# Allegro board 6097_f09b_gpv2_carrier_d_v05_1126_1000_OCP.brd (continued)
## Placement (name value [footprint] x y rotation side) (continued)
R3205  27  [R0402]  74.14 58.86 0 top
R3206  27  [R0402]  74.14 60.13 0 top
R3207  27  [R0402]  74.14 61.65 0 top
R3208  27  [R0402]  74.14 62.92 0 top
R3209  27  [R0402]  74.14 64.45 0 top
R3210  27  [R0402]  74.14 65.72 0 top
R3212  33  [R0402]  83.6 33.14 0 top
R3213  33  [R0402]  80.9 31.7 270 top
R3214  33  [R0402]  92.58 32.88 0 top
R3215  33  [R0402]  79.76 31.7 90 top
R3216  4.75K  [R0402]  79.76 25.6 0 top
R3217  4.75K  [R0402]  81.92 31.7 270 top
R3218  1K  [R0402]  118.92 44.15 90 top
R3219  10K  [R0402]  89.2 37.47 180 top
R3220  1K  [R0402]  92.58 33.9 0 top
R3227  1M  [R0402]  115.49 39.7 270 top
R3228  1.69K  [R0402]  112.7 38.18 0 top
R3230  1K  [R0402]  125.91 37.41 180 top
R3231  1K  [R0402]  128.32 37.41 0 top
R3232  1K  [R0402]  125.91 36.4 180 top
R3233  1K  [R0402]  128.32 36.4 0 top
R3234  1K  [R0402]  125.88 41.48 180 top
R3235  1K  [R0402]  125.88 42.49 0 top
R3236  1K  [R0402]  124.16 44.15 270 top
R3237  1K  [R0402]  123.13 44.15 90 top
R3238  2.2K  [R0402]  131.79 36.12 0 top
R3239  2.2K  [R0402]  131.79 37.15 0 top
R3240  1K  [R0402]  128.32 35.38 0 top
R3241  100  [R0402]  194.11 80.04 0 bottom
R3242  0  [R0402]  81.73 33.94 180 top
R3250  33  [R0402]  205.39 53.57 0 top
R3251  33  [R0402]  202.69 51.65 270 bottom
R3252  33  [R0402]  203.79 51.67 270 bottom
R3253  33  [R0402]  201.55 50.89 270 bottom
R3254  33  [R0402]  200.47 50.91 270 bottom
R3255  33  [R0402]  205.37 54.66 0 top
R3256  4.7K  [R0402]  192.46 83.57 90 bottom
R3257  4.7K  [R0402]  200.75 83.3 180 bottom
R3258  4.7K  [R0402]  207.85 101.68 270 top
R3259  4.7K  [R0402]  207.92 58.93 0 top
R3260  4.7K  [R0402]  205.79 100.66 0 top
R3261  4.7K  [R0402]  205.79 99.57 0 top
R3264  15K  [R0402]  9.83 100.97 0 top
R3265  1K  [R0402]  9.83 105.24 0 top
R3266  33  [R0402]  9.83 102.03 180 top
R3268  150  [R0402]  9.84 106.31 180 top
R3269  150  [R0402]  206.73 108.08 90 top
R3270  0  [R0402]  9.83 103.13 180 top
R3271  4.75K  [R0402]  9.83 104.2 180 top
R3272  4.75K  [R0402]  192.58 73.03 270 bottom
R3273  4.75K  [R0402]  191.53 73.03 270 bottom
R3274  33  [R0402]  186.36 137.69 0 top
R3275  4.75K  [R0402]  186.36 135.62 0 top
R3276  4.75K  [R0402]  186.36 136.67 0 top
R3277  4.75K  [R0402]  181.93 131.06 0 top
R3278  4.75K  [R0402]  181.49 135.94 90 top
R3279  4.75K  [R0402]  181.5 137.87 270 top
R3280  33  [R0402]  186.36 133.58 0 top
R3281  0  [R0402]  205.79 102.74 180 top
R3282  0  [R0402]  205.79 103.76 180 top
R3284  4.75K  [R0402]  193.65 73.03 270 bottom
R3285  4.7K  [R0402]  205.79 101.7 0 top
R3287  22  [R0402]  200.95 84.92 270 bottom
R3288  22  [R0402]  203.65 84.85 270 bottom
R3289  22  [R0402]  202.17 84.77 270 bottom
R3290  22  [R0402]  206.5 70.98 0 top
R3291  22  [R0402]  206.5 68.95 0 top
R3292  22  [R0402]  206.5 72 0 top
R3293  22  [R0402]  206.5 69.96 0 top
R3294  22  [R0402]  205.49 70.1 0 bottom
R3295  22  [R0402]  205.49 73.15 0 bottom
R3296  22  [R0402]  205.49 72.14 0 bottom
R3297  22  [R0402]  205.49 71.12 0 bottom
R3298  22  [R0402]  205.49 69.09 0 bottom
R3301  4.7K  [R0402]  17.6 65.33 90 top
R3302  4.7K  [R0402]  16.59 65.33 90 top
R3332  33  [R0402]  143.15 44.65 180 bottom
R3333  33  [R0402]  143.15 43.51 180 bottom
R3334  33  [R0402]  128.42 42.62 180 bottom
R3335  33  [R0402]  128.42 41.1 180 bottom
R3336  1K  [R0402]  147.09 44.65 0 bottom
R3337  1K  [R0402]  147.09 43.51 0 bottom
R3430  4.7K  [R0402]  178.44 119.17 90 bottom
R3431  4.7K  [R0402]  179.65 119.2 90 bottom
R3432  4.7K  [R0402]  181.01 119.21 90 bottom
R3433  1K  [R0402]  178.43 116.94 270 bottom
R3434  1K  [R0402]  179.65 116.94 270 bottom
R3435  1K  [R0402]  181.01 116.92 270 bottom
R3437  412  [R0402]  96.21 144.89 90 top
R3474  0  [R0402]  23.38 19.68 180 top
R3511  22  [R0402]  23.83 85.75 270 bottom
R3512  22  [R0402]  19.68 85.72 270 bottom
R3513  22  [R0402]  15.57 85.72 270 bottom
R3514  22  [R0402]  15.77 98.86 90 bottom
R3515  22  [R0402]  181.88 128.93 0 top
R3516  22  [R0402]  20.07 103.27 180 top
R3517  22  [R0402]  172.62 125.3 180 top
R3518  22  [R0402]  172.62 122.25 180 top
R3519  22  [R0402]  185.7 120.35 0 top
R3520  22  [R0402]  20.08 102.24 180 top
R3521  22  [R0402]  190.78 124.41 0 top
R3522  22  [R0402]  190.78 126.44 0 top
R3523  22  [R0402]  181.88 129.94 180 top
R3524  22  [R0402]  181.88 125.88 180 top
R3525  22  [R0402]  172.62 123.27 0 top
R3526  22  [R0402]  186.72 123.39 180 top
R3527  22  [R0402]  186.72 125.43 180 top
R3528  22  [R0402]  186.72 127.46 180 top
R3529  22  [R0402]  28.86 88.52 180 bottom
R3530  22  [R0402]  22.76 85.72 90 bottom
R3531  22  [R0402]  18.67 85.72 90 bottom
R3532  22  [R0402]  18.85 98.86 270 bottom
R3533  22  [R0402]  21.89 98.86 270 bottom
R3534  22  [R0402]  26.82 96.88 180 bottom
R3535  100K  [R0402]  22.45 117.01 270 top
R3536  100K  [R0402]  47.14 116.71 270 top
R3537  100K  [R0402]  72.03 115.54 270 top
R3538  100K  [R0402]  97.44 116.34 270 top
R3539  100K  [R0402]  121.25 116.47 270 top
R3540  100K  [R0402]  148.98 115.92 270 top
R3541  100K  [R0402]  40.67 118.08 270 bottom
R3542  100K  [R0402]  63.34 115.31 270 bottom
R3543  100K  [R0402]  87.39 115.37 270 bottom
R3544  100K  [R0402]  113.72 115.46 270 bottom
R3545  100K  [R0402]  137.35 116.01 270 bottom
R3546  100K  [R0402]  164.61 118.76 270 bottom
R3551  0  [R0402]  197.1 34.74 0 top
R3552  22  [R0402]  197.1 33.73 0 top
R3565  4.7K  [R0402]  205.79 93.09 0 top
R3566  4.7K  [R0402]  205.79 94.18 0 top
R3567  4.7K  [R0402]  205.79 92.02 0 top
R3568  4.7K  [R0402]  205.79 90.98 0 top
R3569  4.7K  [R0402]  205.79 97.36 0 top
R3570  4.7K  [R0402]  205.79 98.45 0 top
R3571  4.7K  [R0402]  195.58 90.35 0 bottom
R3572  4.7K  [R0402]  205.79 95.28 0 top
R3573  4.7K  [R0402]  192.61 88.09 0 bottom
R3574  4.7K  [R0402]  205.79 96.32 0 top
R3575  4.7K  [R0402]  192.54 89.2 0 bottom
R3576  4.7K  [R0402]  194.01 88.06 270 bottom
R3577  0  [R0402]  52.43 66.21 180 top
R3578  0  [R0402]  52.43 64.94 180 top
R3579  0  [R0402]  52.43 63.41 180 top
R3580  0  [R0402]  52.43 62.14 180 top
R3581  0  [R0402]  52.43 60.62 180 top
R3582  0  [R0402]  52.43 59.35 180 top
R3583  0  [R0402]  52.43 57.82 180 top
R3584  0  [R0402]  52.43 56.55 180 top
R3585  0  [R0402]  58.35 50.3 270 top
R3586  0  [R0402]  59.62 50.3 270 top
R3587  0  [R0402]  61.4 50.3 270 top
R3588  0  [R0402]  62.67 50.3 270 top
R3589  0  [R0402]  64.32 50.3 270 top
R3590  0  [R0402]  65.59 50.3 270 top
R3591  0  [R0402]  67.12 50.3 270 top
R3592  0  [R0402]  68.39 50.3 270 top
R3593  0  [R0402]  76.3 56.06 0 top
R3594  0  [R0402]  76.3 57.33 0 top
R3595  0  [R0402]  76.3 58.86 0 top
R3596  0  [R0402]  76.3 60.13 0 top
R3597  0  [R0402]  76.3 61.65 0 top
R3598  0  [R0402]  76.3 62.92 0 top
R3599  0  [R0402]  76.3 64.45 0 top
R3600  0  [R0402]  76.3 65.72 0 top
R3601  4.7K  [R0402]  92.55 40.74 0 top
R3618  22  [R0402]  23.38 18.52 180 top
R3619  4.7K  [R0402]  34.42 110.41 90 top
R3620  22  [R0402]  41.3 113.26 270 top
R3621  22  [R0402]  40.13 110.44 180 top
R3622  4.7K  [R0402]  33.32 110.41 90 top
R3623  0.005  [R1206XK]  27.91 116.08 270 top
R3625  10  [R0402]  30.73 115.54 0 top
R3626  10  [R0402]  30.73 116.59 0 top
R3628  22  [R0402]  63.14 110.21 270 top
R3629  22  [R0402]  62.09 110.21 270 top
R3630  4.7K  [R0402]  56.3 113.84 0 top
R3631  0.005  [R1206XK]  52.65 116.41 270 top
R3632  10  [R0402]  55.39 115.77 0 top
R3633  10  [R0402]  55.39 116.79 0 top
R3634  4.7K  [R0402]  81.1 112.15 0 top
R3635  22  [R0402]  88.51 110.6 270 top
R3636  22  [R0402]  87.49 110.6 270 top
R3638  0.005  [R1206XK]  77.53 115.02 270 top
R3639  10  [R0402]  80.17 114.81 0 top
R3640  10  [R0402]  80.17 115.88 0 top
R3642  22  [R0402]  111.87 108.88 270 top
R3643  22  [R0402]  110.64 108.88 270 top
R3645  0.005  [R1206XK]  102.94 115.72 270 top
R3646  10  [R0402]  105.41 114.92 0 top
R3647  10  [R0402]  105.41 115.96 0 top
R3649  22  [R0402]  137.57 109.78 270 top
R3650  22  [R0402]  136.53 109.78 270 top
R3651  4.7K  [R0402]  130.15 111.7 90 top
R3652  0.005  [R1206XK]  126.87 115.91 270 top
R3653  10  [R0402]  129.31 115.05 0 top
R3654  10  [R0402]  129.31 116.09 0 top
R3656  22  [R0402]  162.89 125.94 90 top
R3657  22  [R0402]  163.93 125.94 90 top
R3658  4.7K  [R0402]  160.98 115.95 90 top
R3659  0.005  [R1206XK]  154.55 116.23 270 top
R3660  10  [R0402]  157.76 115.45 0 top
R3661  10  [R0402]  157.76 116.54 0 top
R3666  22  [R0402]  32.45 108.07 0 bottom
R3667  22  [R0402]  30.43 109.66 0 bottom
R3669  0.005  [R1206XK]  34.62 116.61 270 bottom
R3670  10  [R0402]  31.51 116.08 180 bottom
R3671  10  [R0402]  31.51 117.11 180 bottom
R3678  4.7K  [R0402]  38.67 110.77 180 bottom
R3691  4.7K  [R0402]  38.35 111.81 180 bottom
R3692  22  [R0402]  47.74 109.96 270 bottom
R3693  22  [R0402]  48.78 109.96 270 bottom
R3694  0.005  [R1206XK]  57.8 115.5 270 bottom
R3695  10  [R0402]  54.82 114.64 180 bottom
R3696  10  [R0402]  54.82 115.68 180 bottom
R3697  4.7K  [R0402]  50.94 109.96 90 bottom
R3698  4.7K  [R0402]  52.03 109.96 90 bottom
R3699  22  [R0402]  74.81 108.72 270 bottom
R3700  22  [R0402]  75.85 108.72 270 bottom
R3701  0.005  [R1206XK]  81.93 114.8 270 bottom
R3702  10  [R0402]  79.54 113.93 180 bottom
R3703  10  [R0402]  79.54 114.97 180 bottom
R3704  4.7K  [R0402]  78.02 108.72 90 bottom
R3705  4.7K  [R0402]  79.13 108.72 90 bottom
R3706  22  [R0402]  98.17 109.04 270 bottom
R3707  22  [R0402]  99.21 109.04 270 bottom
R3708  0.005  [R1206XK]  107.58 114.83 270 bottom
R3709  10  [R0402]  104.89 113.97 180 bottom
R3710  10  [R0402]  104.89 115.01 180 bottom
R3711  4.7K  [R0402]  101.35 109.04 90 bottom
R3712  4.7K  [R0402]  102.41 109.04 90 bottom
R3713  4.7K  [R0402]  56.3 112.78 0 top
R3714  22  [R0402]  123.45 105.66 0 bottom
R3715  22  [R0402]  123.45 106.7 0 bottom
R3716  0.005  [R1206XK]  131.4 115.29 270 bottom
R3717  10  [R0402]  128.74 114.43 180 bottom
R3718  10  [R0402]  128.74 115.47 180 bottom
R3719  4.7K  [R0402]  124.76 109.36 90 bottom
R3720  4.7K  [R0402]  125.79 109.36 90 bottom
R3721  22  [R0402]  149.23 112.44 270 bottom
R3722  22  [R0402]  150.27 112.44 270 bottom
R3723  0.005  [R1206XK]  158.82 118.18 270 bottom
R3724  10  [R0402]  156.32 117.6 180 bottom
R3725  10  [R0402]  156.32 118.64 180 bottom
R3726  4.7K  [R0402]  154.44 112.43 90 bottom
R3727  4.7K  [R0402]  155.53 112.43 90 bottom
R3728  4.7K  [R0402]  81.1 113.26 0 top
R3729  4.7K  [R0402]  106.76 111.57 90 top
R3730  4.7K  [R0402]  108.15 110.14 0 top
R3731  4.7K  [R0402]  132.08 110.44 0 top
R3732  4.7K  [R0402]  162 115.95 90 top
R3745  4.75K  [R0402]  50.37 29.51 90 bottom
R3746  10  [R0402]  51.47 29.51 270 bottom
R3747  4.75K  [R0402]  55.07 38.56 270 bottom
R3748  22  [R0402]  56.16 38.56 270 bottom
R3749  4.75K  [R0402]  45.79 29.51 90 bottom
R3750  10  [R0402]  47.88 29.51 270 bottom
R3751  4.75K  [R0402]  52.53 38.56 270 bottom
R3752  22  [R0402]  53.7 38.56 270 bottom
R3753  4.75K  [R0402]  54.74 29.51 90 bottom
R3754  10  [R0402]  56.79 29.51 270 bottom
R3755  4.75K  [R0402]  57.23 38.56 270 bottom
R3756  22  [R0402]  58.42 38.61 270 bottom
R3757  22  [R0402]  49.28 29.51 90 bottom
R3758  22  [R0402]  44.75 29.51 90 bottom
R3759  22  [R0402]  53.72 29.51 90 bottom
R3764  22  [R0402]  32.28 40.87 0 top
R3765  10K  [R0402]  32.36 35.51 90 top
R3766  0.51  [R0402]  29.69 37.57 90 top
R3767  22  [R0402]  34.81 39.53 0 bottom
R3768  22  [R0402]  34.06 36.4 90 bottom
R3769  22  [R0402]  53.34 51.08 180 bottom
R3770  22  [R0402]  53.37 49.99 180 bottom
R3771  22  [R0402]  39.17 36.42 90 top
R3772  22  [R0402]  45.42 36.45 90 top
R3773  22  [R0402]  33.57 56.59 270 top
R3774  22  [R0402]  34.67 56.59 270 top
R3775  22  [R0402]  35.76 56.59 270 top
R3776  22  [R0402]  36.86 56.59 270 top
R3777  22  [R0402]  47.45 36.45 90 bottom
R3778  22  [R0402]  48.46 36.45 90 top
R3779  22  [R0402]  52.73 42.88 180 top
R3780  22  [R0402]  52.73 43.89 180 top
R3781  22  [R0402]  52.73 40.84 180 bottom
R3782  22  [R0402]  52.73 40.84 180 top
R3783  22  [R0402]  50.57 41.86 180 top
R3784  22  [R0402]  52.73 41.86 180 top
R3786  1K  [R0402]  34.81 38.51 0 bottom
R3787  1K  [R0402]  35.13 36.4 90 bottom
R3788  1K  [R0402]  51.21 51.08 0 bottom
R3789  1K  [R0402]  51.21 49.99 0 bottom
R3790  2.2K  [R0402]  40.21 36.42 90 top
R3791  2.2K  [R0402]  44.4 36.45 90 top
R3792  2.2K  [R0402]  33.57 54.56 90 top
R3793  2.2K  [R0402]  34.67 54.56 90 top
R3794  2.2K  [R0402]  35.76 54.56 90 top
R3795  2.2K  [R0402]  36.86 54.56 90 top
R3796  2.2K  [R0402]  46.43 36.45 90 bottom
R3797  2.2K  [R0402]  47.45 36.45 90 top
R3798  2.2K  [R0402]  50.57 42.88 0 top
R3799  2.2K  [R0402]  50.57 43.89 0 top
R3800  2.2K  [R0402]  50.57 40.84 0 bottom
R3801  2.2K  [R0402]  50.57 40.84 0 top
R3802  220  [R0402]  40.03 54.56 270 top
R3803  10K  [R0402]  10.57 43.49 270 top
R3804  22  [R0402]  21.67 65.33 90 top
R3805  22  [R0402]  22.68 65.33 90 top
R3806  220  [R0402]  23.42 80.11 90 top
R3807  220  [R0402]  20.65 65.33 270 top
R3808  4.7K  [R0402]  22.25 82.17 270 top
R3809  22  [R0402]  29.81 109.75 90 top
R3810  22  [R0402]  30.86 109.7 90 top
R3811  22  [R0402]  56.74 107.46 90 bottom
R3812  22  [R0402]  55.66 109.03 90 bottom
R3813  22  [R0402]  83.8 106.16 90 bottom
R3814  22  [R0402]  82.26 108.26 0 bottom
R3815  22  [R0402]  101.67 105.42 180 bottom
R3816  22  [R0402]  100.63 106.88 0 bottom
R3817  22  [R0402]  30.3 61.64 90 top
R3818  22  [R0402]  31.32 61.64 90 top
R3819  220  [R0402]  31.88 76.22 270 top
R3820  220  [R0402]  29.29 61.64 270 top
R3821  4.7K  [R0402]  30.86 78 270 top
R3822  4.7K  [R0402]  28.27 61.64 90 top
R3823  4.7K  [R0402]  27.25 61.64 90 top
R3824  4.7K  [R0402]  25.22 61.64 90 top
R3825  4.7K  [R0402]  26.24 61.64 90 top
R3826  22  [R0402]  128.57 108.05 0 top
R3827  22  [R0402]  129.29 109.62 90 top
R3828  22  [R0402]  148.79 120.21 90 bottom
R3829  22  [R0402]  147.64 120.21 90 bottom
R3830  22  [R0402]  37.62 61.62 90 top
R3831  22  [R0402]  38.64 61.62 90 top
R3832  220  [R0402]  39.19 76.2 270 top
R3833  220  [R0402]  36.6 61.62 270 top
R3834  4.7K  [R0402]  38.18 77.98 270 top
R3835  4.7K  [R0402]  35.59 61.62 90 top
R3836  4.7K  [R0402]  34.57 61.62 90 top
R3837  4.7K  [R0402]  32.54 61.62 90 top
R3838  4.7K  [R0402]  33.56 61.62 90 top
R3839  22  [R0402]  155.46 105.36 180 bottom
R3840  22  [R0402]  157.17 106.47 180 bottom
R3841  22  [R0402]  140.66 108.34 0 top
R3842  22  [R0402]  142.1 109.64 180 top
R3843  22  [R0402]  25.44 26.67 180 top
R3844  22  [R0402]  25.44 27.68 180 top
R3845  220  [R0402]  25.55 40.64 90 top
R3846  220  [R0402]  23.04 32.99 90 bottom
R3847  4.7K  [R0402]  24.54 38.81 90 top
R3848  4.7K  [R0402]  22.02 32.99 270 bottom
R3849  4.7K  [R0402]  21.01 32.99 270 bottom
R3850  4.7K  [R0402]  18.97 32.99 270 bottom
R3851  4.7K  [R0402]  19.99 32.99 270 bottom
R3852  22  [R0402]  113.37 106.99 180 top
R3853  22  [R0402]  112.87 104.32 180 top
R3854  22  [R0402]  86.31 106.04 0 top
R3855  22  [R0402]  85.38 103.23 180 top
R3856  22  [R0402]  45.21 61.62 90 top
R3857  22  [R0402]  46.23 61.62 90 top
R3858  220  [R0402]  47.8 76.2 270 top
R3859  220  [R0402]  44.2 61.62 270 top
R3860  4.7K  [R0402]  46.79 76.2 90 top
R3861  4.7K  [R0402]  43.18 61.62 90 top
R3862  4.7K  [R0402]  42.16 61.62 90 top
R3863  4.7K  [R0402]  40.13 61.62 90 top
R3864  4.7K  [R0402]  41.15 61.62 90 top
R3865  22  [R0402]  62.63 106.15 270 bottom
R3866  22  [R0402]  61.59 106.73 270 bottom
R3867  22  [R0402]  43.36 107.98 0 top
R3868  22  [R0402]  40.79 107.89 180 top
R3869  22  [R0402]  29.82 80.85 90 top
R3870  22  [R0402]  30.84 80.85 90 top
R3871  220  [R0402]  31.39 95.43 270 top
R3872  220  [R0402]  28.8 80.85 270 top
R3873  4.7K  [R0402]  30.38 97.21 270 top
R3874  4.7K  [R0402]  27.79 80.85 90 top
R3875  4.7K  [R0402]  26.77 80.85 90 top
R3876  4.7K  [R0402]  24.74 80.85 90 top
R3877  4.7K  [R0402]  25.76 80.85 90 top
R3878  22  [R0402]  10.31 30.55 180 top
R3879  22  [R0402]  10.28 29.32 180 top
R3880  22  [R0402]  38.12 37.19 270 bottom
R3881  22  [R0402]  10.13 27.91 180 top
R3882  4.7K  [R0402]  8.1 31.8 0 top
R3883  4.7K  [R0402]  8.13 30.48 0 top
R3884  4.7K  [R0402]  8.13 27.91 0 top
R3885  22  [R0402]  52.48 43.18 270 bottom
R3887  4.7K  [R0402]  134.03 110.02 0 top
R3888  4.7K  [R0402]  165.02 125.92 90 top
R3889  4.7K  [R0402]  36.68 110.52 0 bottom
R3890  4.7K  [R0402]  53.59 108.48 90 bottom
R3891  4.7K  [R0402]  79.36 105.14 180 bottom
R3892  4.7K  [R0402]  104.8 107.34 180 bottom
R3893  4.7K  [R0402]  124.9 107.57 90 bottom
R3894  4.7K  [R0402]  153.16 109.55 0 bottom
R3899  4.7K  [R0402]  37.89 110.77 0 top
R3900  4.7K  [R0402]  56.44 111.68 180 top
R3901  4.7K  [R0402]  85.98 110.97 180 top
R3902  4.7K  [R0402]  108.43 108.51 0 top
R3903  51K  [R0402]  53.62 45.54 270 top
R3904  10K  [R0402]  52.6 45.54 90 top
R3905  8.25K  [R0402]  54.76 42.88 0 top
R3906  0  [R0402]  53.62 47.32 90 top
R3908  5.11K  [R0402]  54.76 41.86 180 top
R3909  10K  [R0402]  53.62 45.54 270 bottom
R3910  34K  [R0402]  52.6 45.54 90 bottom
R3911  22  [R0402]  46.15 56.57 90 bottom
R3912  22  [R0402]  49.48 55.84 90 bottom
R3913  10K  [R0402]  7.77 38.56 180 top
R3914  10K  [R0402]  8.03 40.97 180 top
R3915  10K  [R0402]  7.77 37.54 180 top
R3916  4.7K  [R0402]  7.9 43 0 top
R3917  22  [R0402]  11.84 39.57 270 bottom
R3918  22  [R0402]  12.88 39.57 270 bottom
R3919  22  [R0402]  14.94 39.6 270 bottom
R3920  22  [R0402]  13.89 39.6 270 bottom
R3921  22  [R0402]  18.01 39.88 270 bottom
R3922  4.7K  [R0402]  23.72 56.77 270 top
R3923  4.7K  [R0402]  20.07 39.65 270 bottom
R3924  22  [R0402]  28.51 49.96 180 bottom
R3925  22  [R0402]  28.53 51.21 180 bottom
R3926  22  [R0402]  28.9 53.95 180 bottom
R3927  22  [R0402]  28.91 52.72 180 bottom
R3928  22  [R0402]  28.89 55.5 180 bottom
R3929  22  [R0402]  28.9 56.98 180 bottom
R3930  22  [R0402]  24.09 50.34 180 top
R3931  22  [R0402]  24.09 52.45 180 top
R3932  22  [R0402]  24.09 53.47 180 top
R3933  22  [R0402]  28.9 57.99 180 bottom
R3934  22  [R0402]  24.09 51.43 180 top
R3935  22  [R0402]  24.09 54.48 180 top
R3936  22  [R0402]  9.91 35.59 270 bottom
R3937  22  [R0402]  15.58 46.25 0 top
R3938  22  [R0402]  13.15 42.24 0 top
R3939  22  [R0402]  3.06 49.01 0 bottom
R3940  22  [R0402]  3.07 44.02 0 bottom
R3941  22  [R0402]  3.07 45.03 0 bottom
R3942  22  [R0402]  3.06 50.03 0 bottom
R3943  22  [R0402]  5.36 47.32 0 top
R3944  22  [R0402]  3.07 46.05 0 bottom
R3945  22  [R0402]  3.06 47.86 0 bottom
R3946  22  [R0402]  3.06 51.05 0 bottom
R3947  22  [R0402]  2.01 52.19 0 bottom
R3948  22  [R0402]  5.36 48.34 0 top
R3949  22  [R0402]  5.36 50.37 0 top
R3950  22  [R0402]  5.36 49.35 0 top
R3951  22  [R0402]  3.44 54.07 0 bottom
R3952  22  [R0402]  5.36 53.42 0 top
R3953  22  [R0402]  5.36 52.4 0 top
R3954  22  [R0402]  3.43 55.82 0 bottom
R3955  22  [R0402]  5.36 56.46 0 top
R3956  22  [R0402]  5.36 55.45 0 top
R3957  22  [R0402]  5.36 58.5 0 top
R3958  22  [R0402]  3.43 56.84 0 bottom
R3959  22  [R0402]  3.43 57.86 0 bottom
R3960  22  [R0402]  5.36 54.43 0 top
R3961  22  [R0402]  5.36 57.48 0 top
R3962  22  [R0402]  3.43 58.87 0 bottom
R3963  22  [R0402]  12.52 65.96 90 bottom
R3964  22  [R0402]  7.95 65.96 90 bottom
R3965  22  [R0402]  9.09 65.96 90 bottom
R3966  22  [R0402]  13.67 65.96 90 bottom
R3967  22  [R0402]  10.31 62.05 90 top
R3968  22  [R0402]  14.81 65.96 90 bottom
R3969  22  [R0402]  15.95 65.96 90 bottom
R3970  22  [R0402]  10.24 65.96 90 bottom
R3971  22  [R0402]  11.38 65.96 90 bottom
R3972  22  [R0402]  12.34 62.05 90 top
R3973  22  [R0402]  17.09 65.96 90 bottom
R3974  22  [R0402]  11.33 62.05 90 top
R3975  22  [R0402]  18.24 65.96 90 bottom
R3976  22  [R0402]  13.36 62.05 90 top
R3977  22  [R0402]  14.38 62.05 90 top
R3978  22  [R0402]  16.41 62.05 90 top
R3979  22  [R0402]  19.38 65.96 90 bottom
R3980  22  [R0402]  17.42 62.05 90 top
R3981  22  [R0402]  18.38 58.37 0 top
R3982  22  [R0402]  21.67 65.96 90 bottom
R3983  22  [R0402]  22.81 65.91 90 bottom
R3984  22  [R0402]  15.39 62.05 90 top
R3985  22  [R0402]  18.44 62.05 90 top
R3986  22  [R0402]  20.52 65.96 90 bottom
R3987  22  [R0402]  16.99 40.04 270 bottom
R3988  22  [R0402]  19.02 39.62 270 bottom
R3989  22  [R0402]  15.98 40.01 270 bottom
R3990  22  [R0402]  37.9 54.56 270 top
R3991  22  [R0402]  34.17 47.7 0 bottom
R3992  22  [R0402]  32.61 45.03 0 bottom
R3993  22  [R0402]  38.36 51.3 270 bottom
R3994  22  [R0402]  41.27 36.45 90 top
R3995  22  [R0402]  40.21 37.21 90 bottom
R3996  22  [R0402]  42.32 36.45 90 top
R3997  22  [R0402]  43.36 36.45 90 top
R3998  22  [R0402]  41.27 37.24 90 bottom
R3999  22  [R0402]  42.32 37.24 90 bottom
R4000  22  [R0402]  38.96 54.56 270 top
R4001  22  [R0402]  38.13 36.1 90 top
R4002  22  [R0402]  46.43 36.45 90 top
R4003  22  [R0402]  48.46 36.45 90 bottom
R4004  22  [R0402]  45.41 36.45 90 bottom
R4005  22  [R0402]  44.4 36.45 90 bottom
R4006  22  [R0402]  39.14 36.53 90 bottom
R4007  22  [R0402]  29.69 44.15 0 top
R4008  22  [R0402]  32.28 42.98 0 bottom
R4009  22  [R0402]  29.77 47.24 0 top
R4010  22  [R0402]  30.57 49.33 0 top
R4011  22  [R0402]  30.57 48.31 0 top
R4012  22  [R0402]  32.28 46.05 0 bottom
R4013  22  [R0402]  29.74 43.14 0 top
R4014  22  [R0402]  29.62 46.22 0 top
R4015  22  [R0402]  29.74 42.12 0 top
R4016  22  [R0402]  37.89 109.75 0 top
R4017  22  [R0402]  56.44 110.59 180 top
R4018  22  [R0402]  85.98 109.93 180 top
R4019  22  [R0402]  106.55 108.51 180 top
R4020  22  [R0402]  132.1 109.39 180 top
R4021  22  [R0402]  163.8 128.4 180 top
R4022  22  [R0402]  36.68 109.49 0 bottom
R4023  22  [R0402]  55.55 106.07 0 bottom
R4024  22  [R0402]  81.21 105.14 0 bottom
R4025  22  [R0402]  106.58 107.34 0 bottom
R4026  22  [R0402]  125.96 107.57 90 bottom
R4027  22  [R0402]  153.16 107.39 0 bottom
R4028  22  [R0402]  32.28 44.02 0 bottom
R4029  22  [R0402]  32.28 41.94 0 bottom
R4030  22  [R0402]  32.28 41.94 0 top
R4031  22  [R0402]  32.28 40.87 0 bottom
R4032  22  [R0402]  52.81 52.98 180 top
R4033  22  [R0402]  53.37 47.96 180 bottom
R4034  22  [R0402]  100.23 41.15 90 bottom
R4035  22  [R0402]  42.21 54.56 90 bottom
R4048  10K  [R0402]  4.09 9.09 0 top
R4049  22  [R0402]  145.19 44.65 0 bottom
R4050  22  [R0402]  145.19 43.51 0 bottom
R4051  1K  [R0402]  45.42 54.42 90 bottom
R4052  1K  [R0402]  48.39 55.84 270 bottom
R4053  22  [R0402]  51.21 48.97 180 bottom
R4054  22  [R0402]  42.21 54.56 270 top
R4055  4.7K  [R0402]  53.37 48.97 180 bottom
R4056  4.7K  [R0402]  42.21 56.39 270 top
R4057  22  [R0402]  6.77 82.6 0 bottom
R4058  22  [R0402]  3.6 84.15 0 bottom
R4059  22  [R0402]  4.01 78.99 90 bottom
R4060  22  [R0402]  2.22 73.28 90 top
R4061  22  [R0402]  7.14 90.45 0 bottom
R4062  22  [R0402]  3.63 90.66 0 bottom
R4063  22  [R0402]  67.57 40.29 270 bottom
R4064  22  [R0402]  65.39 40.29 270 bottom
R4065  4.75K  [R0402]  71.86 33.55 90 bottom
R4066  10  [R0402]  74.9 33.55 270 bottom
R4067  4.75K  [R0402]  66.46 40.29 270 bottom
R4068  22  [R0402]  72.87 33.55 90 bottom
R4069  4.75K  [R0402]  67.79 33.55 90 bottom
R4070  10  [R0402]  70.84 33.55 270 bottom
R4071  4.75K  [R0402]  64.28 40.29 270 bottom
R4072  22  [R0402]  68.81 33.55 90 bottom
R4073  4.7K  [R0402]  208 88.69 0 top
R4074  4.7K  [R0402]  208 89.77 0 top
R4075  1K  [R0402]  205.92 88.69 180 top
R4076  1K  [R0402]  205.92 89.77 180 top
R4077  47  [R0402]  3.61 83.07 0 bottom
R4078  47  [R0402]  6.77 83.64 0 bottom
R4079  47  [R0402]  4.55 74.5 90 bottom
R4080  47  [R0402]  1.96 78.99 270 bottom
R4081  47  [R0402]  3.63 89.58 0 bottom
R4082  47  [R0402]  11.13 93.55 0 top
R4083  47  [R0402]  3.67 92.74 0 bottom
R4084  47  [R0402]  8.23 95.91 0 bottom
R4085  47  [R0402]  3.6 86.24 0 bottom
R4086  47  [R0402]  7.14 88.87 0 bottom
R4087  47  [R0402]  3.73 96.93 0 bottom
R4088  47  [R0402]  8.23 99.31 0 bottom
R4089  22  [R0402]  8.23 94.89 0 bottom
R4090  22  [R0402]  3.78 94.79 0 bottom
R4091  22  [R0402]  6.99 87.05 0 bottom
R4092  22  [R0402]  3.6 87.32 180 bottom
R4093  22  [R0402]  8.23 98.27 0 bottom
R4094  22  [R0402]  3.71 98.98 0 bottom
R4095  22  [R0402]  14.59 48.32 180 top
R4096  22  [R0402]  14.83 43.54 270 top
R4097  1K  [R0402]  95.15 144.89 270 top
R4098  4.7K  [R0201]  21.55 123.27 90 top
R4099  4.7K  [R0201]  20.63 123.27 90 top
R4100  4.7K  [R0201]  22.91 133.15 180 bottom
R4101  4.7K  [R0201]  24.37 133.15 0 bottom
R4102  4.7K  [R0201]  51.16 145.04 180 bottom
R4103  4.7K  [R0201]  53.07 145.04 180 bottom
R4104  4.7K  [R0201]  53.07 143.99 0 bottom
R4105  4.7K  [R0201]  51.16 143.99 0 bottom
R4106  4.7K  [R0201]  62.21 145.09 180 bottom
R4107  4.7K  [R0201]  60.31 145.09 180 bottom
R4108  4.7K  [R0201]  60.31 144.04 0 bottom
R4109  4.7K  [R0201]  62.21 144.04 0 bottom
R4110  4.7K  [R0201]  70.04 145.06 180 bottom
R4111  4.7K  [R0201]  68.39 145.01 180 bottom
R4112  4.7K  [R0201]  68.39 143.96 0 bottom
R4113  4.7K  [R0201]  70.04 144.01 0 bottom
R4114  4.7K  [R0201]  130.82 145.09 0 top
R4115  4.7K  [R0201]  129.23 143.08 180 top
R4116  4.7K  [R0201]  127.85 143.08 180 top
R4117  4.7K  [R0201]  130.82 144.04 180 top
R4118  4.7K  [R0201]  143.9 144.56 180 bottom
R4119  4.7K  [R0201]  142.17 144.58 0 bottom
R4120  4.7K  [R0201]  142.17 143.61 180 bottom
R4121  4.7K  [R0201]  143.9 143.58 0 bottom
R4122  4.7K  [R0201]  172.43 126.87 90 bottom
R4123  4.7K  [R0201]  171.37 126.87 90 bottom
R4124  4.7K  [R0201]  171.38 128.69 90 bottom
R4125  4.7K  [R0201]  172.44 128.69 90 bottom
R4126  4.7K  [R0201]  146.25 144.61 0 bottom
R4127  4.7K  [R0201]  147.97 144.59 180 bottom
R4128  4.7K  [R0201]  147.97 143.62 0 bottom
R4129  4.7K  [R0201]  146.25 143.64 180 bottom
R4130  4.7K  [R0201]  127.86 145.09 0 top
R4131  4.7K  [R0201]  129.24 145.09 180 top
R4132  4.7K  [R0201]  129.24 144.04 0 top
R4133  4.7K  [R0201]  127.86 144.04 180 top
R4134  4.7K  [R0201]  71.71 145.09 180 bottom
R4135  4.7K  [R0201]  73.39 145.09 180 bottom
R4136  4.7K  [R0201]  73.39 144.04 0 bottom
R4137  4.7K  [R0201]  71.71 144.04 0 bottom
R4138  4.7K  [R0201]  65.08 144.99 180 bottom
R4139  4.7K  [R0201]  66.73 144.99 180 bottom
R4140  4.7K  [R0201]  66.73 143.93 0 bottom
R4141  4.7K  [R0201]  65.08 143.93 0 bottom
R4142  4.7K  [R0201]  48.1 129.65 180 bottom
R4143  4.7K  [R0201]  48.1 130.57 180 bottom
R4144  4.7K  [R0201]  47.84 144.12 0 bottom
R4145  4.7K  [R0201]  47.79 145.19 0 bottom
R4146  22  [R0402]  74 49.33 180 bottom
R4147  22  [R0402]  74 50.36 180 bottom
R4148  22  [R0402]  74 51.38 180 bottom
R4149  22  [R0402]  74 52.41 180 bottom
R4150  22  [R0402]  73.99 53.45 180 bottom
R4151  22  [R0402]  73.99 54.5 180 bottom
R4152  22  [R0402]  75.09 57.18 90 bottom
R4153  22  [R0402]  76.13 57.18 90 bottom
R4154  22  [R0402]  79.88 56.65 90 bottom
R4155  22  [R0402]  80.9 56.65 90 bottom
R4156  22  [R0402]  81.93 56.65 90 bottom
R4157  22  [R0402]  83.35 55.62 90 bottom
R4158  220  [R0402]  84.42 49.94 90 bottom
R4159  22  [R0402]  82.11 46.35 90 bottom
R4160  22  [R0402]  83.13 46.35 90 bottom
R4161  220  [R0402]  77.8 46.35 90 bottom
R4162  220  [R0402]  76.76 46.35 90 bottom
R4163  4.7K  [R0402]  78.84 46.35 270 bottom
R4164  22  [R0402]  181.61 126.67 180 bottom
R4165  22  [R0402]  186.38 136.32 180 bottom
R4166  22  [R0402]  184.68 130.99 180 bottom
R4167  22  [R0402]  191.9 127.18 90 bottom
R4168  22  [R0402]  193.29 104.8 0 bottom
R4169  22  [R0402]  190.47 143.51 90 bottom
R4170  22  [R0402]  188.09 143.51 90 bottom
R4171  22  [R0402]  185.83 124.77 90 bottom
R4172  22  [R0402]  188.16 121.72 90 bottom
R4173  22  [R0402]  191.62 143.51 90 bottom
R4174  22  [R0402]  189.2 121.72 90 bottom
R4175  22  [R0402]  189.28 143.51 90 bottom
R4182  4.7K  [R0402]  184.68 129.92 180 bottom
R4183  4.7K  [R0402]  191.9 125.4 270 bottom
R4184  4.7K  [R0402]  190.47 141.66 270 bottom
R4185  4.7K  [R0402]  191.62 141.66 270 bottom
R4186  4.7K  [R0402]  181.61 125.58 180 bottom
R4187  4.7K  [R0402]  186.36 134.59 180 bottom
R4188  4.7K  [R0402]  185.83 122.96 270 bottom
R4189  4.7K  [R0402]  188.16 119.81 270 bottom
R4190  4.7K  [R0402]  189.2 119.84 270 bottom
R4191  4.7K  [R0402]  189.28 141.63 270 bottom
R4192  4.7K  [R0402]  193.29 105.89 0 bottom
R4193  4.7K  [R0402]  188.09 141.63 270 bottom
R4194  22  [R0402]  32.23 86.33 90 top
R4195  22  [R0402]  35.38 81.33 180 top
R4196  22  [R0402]  40.79 81.36 0 top
R4197  22  [R0402]  89.26 60.78 180 top
R4198  22  [R0402]  93.04 55.22 180 top
R4199  22  [R0402]  89.26 58.37 180 top
R4200  22  [R0402]  102.69 56.95 0 top
R4201  22  [R0402]  102.67 60.12 0 top
R4202  22  [R0402]  40.21 87.91 0 top
R4203  22  [R0402]  89.26 55.19 180 top
R4204  22  [R0402]  40.18 85.62 0 top
R4205  22  [R0402]  31.93 91.03 90 top
R4206  4.7K  [R0402]  38.96 81.36 180 top
R4207  4.7K  [R0402]  89.26 59.49 180 top
R4208  4.7K  [R0402]  89.26 57.33 180 top
R4209  4.7K  [R0402]  89.26 56.29 180 top
R4210  4.7K  [R0402]  32.23 84.51 270 top
R4211  4.7K  [R0402]  37.16 81.33 0 top
R4212  4.7K  [R0402]  102.67 59.06 0 top
R4213  4.7K  [R0402]  40.21 88.95 0 top
R4214  4.7K  [R0402]  40.18 86.67 0 top
R4215  4.7K  [R0402]  31.93 89.23 270 top
R4216  4.7K  [R0402]  94.87 55.22 0 top
R4217  4.7K  [R0402]  102.69 58.04 0 top
R4218  10K  [R0402]  8.28 28.02 270 bottom
R4219  0  [R0603]  2.39 38.68 0 bottom
R4220  100K  [R0402]  2.18 33.81 0 bottom
R4221  100K  [R0402]  3.96 33.81 0 bottom
R4222  100K  [R0402]  7.24 28.02 270 bottom
R4223  100K  [R0402]  5.74 33.83 0 bottom
R4224  100K  [R0402]  7.59 33.83 0 bottom
R4225  100K  [R0402]  13.06 28.14 270 bottom
R4226  10K  [R0402]  12.04 28.14 270 bottom
R4227  0  [R0603]  6.4 38.68 180 bottom
R4228  22  [R0402]  53.34 49.12 180 top
R4229  22  [R0402]  53.34 50.17 180 top
R4230  10K  [R0402]  9.35 28.02 90 bottom
R4231  10K  [R0402]  14.25 28.14 90 bottom
R4232  22  [R0402]  111.16 143.83 90 top
R4233  1K  [R0402]  109.25 146.41 180 top
R4234  0  [R0402]  21.98 135.87 270 bottom
R4235  0  [R0402]  37.03 136.17 0 top
R4236  0  [R0402]  50.67 122.33 90 top
R4237  0  [R0402]  61.83 135.97 180 top
R4238  0  [R0402]  75.18 122.37 90 top
R4239  0  [R0402]  79.62 136.06 0 top
R4240  0  [R0402]  77.35 144.25 180 bottom
R4241  0  [R0402]  110.13 136.13 180 top
R4242  0  [R0402]  122.22 121.88 90 top
R4243  0  [R0402]  133.77 136.02 0 top
R4244  0  [R0402]  147.02 121.34 90 top
R4245  0  [R0402]  155.88 135.98 0 top
R4246  0  [R0402]  160.54 125.18 90 bottom
R4247  0  [R0402]  150.67 143.96 270 bottom
R4248  0  [R0402]  149.58 143.99 270 bottom
R4249  0  [R0402]  128.51 145.04 180 bottom
R4250  0  [R0402]  112.84 125.57 0 bottom
R4251  0  [R0402]  95.19 143.22 0 top
R4252  0  [R0402]  89.63 125.27 90 bottom
R4253  0  [R0402]  77.35 143.24 180 bottom
R4254  0  [R0402]  77.35 145.28 180 bottom
R4255  0  [R0402]  54.77 143.3 180 bottom
R4256  0  [R0402]  34.89 145.61 0 bottom
R4257  0  [R0402]  29.62 143.9 180 bottom
R4258  33  [R0402]  198.33 7.56 90 bottom
R4259  33  [R0402]  199.07 10.92 0 bottom
R4260  33  [R0402]  194.03 17.17 270 bottom
R4261  33  [R0402]  192.97 17.17 270 bottom
R4262  4.7K  [R0402]  30.71 121.11 270 top
R4263  4.7K  [R0402]  53.24 121.37 270 top
R4264  4.7K  [R0402]  77.5 120.73 270 top
R4265  4.7K  [R0402]  98.99 121.1 270 top
R4266  4.7K  [R0402]  125.92 121.26 270 top
R4267  4.7K  [R0402]  148.52 120.55 270 top
R4268  4.7K  [R0402]  156.74 124.2 270 bottom
R4269  4.7K  [R0402]  135.92 124.2 270 bottom
R4270  4.7K  [R0402]  111.28 124.16 270 bottom
R4271  4.7K  [R0402]  88.24 124.21 270 bottom
R4272  4.7K  [R0402]  64.28 123.7 270 bottom
R4273  4.7K  [R0402]  41.59 123.15 270 bottom
R4274  4.7K  [R0402]  17.76 44.93 0 top
R4275  4.7K  [R0402]  8.59 82.6 180 bottom
R4276  4.7K  [R0402]  6.76 84.73 180 bottom
R4277  4.7K  [R0402]  2.97 78.99 90 bottom
R4278  4.7K  [R0402]  3.3 73.28 90 top
R4279  4.7K  [R0402]  7.14 91.52 0 bottom
R4280  4.7K  [R0402]  7.11 92.56 180 bottom
R4281  4.7K  [R0402]  10.03 94.89 180 bottom
R4282  4.7K  [R0402]  3.78 93.78 0 bottom
R4283  4.7K  [R0402]  6.99 86.03 0 bottom
R4284  4.7K  [R0402]  1.55 88.27 270 top
R4285  4.7K  [R0402]  8.23 97.26 0 bottom
R4286  4.7K  [R0402]  3.71 97.97 0 bottom
R4287  100K  [R0402]  103.41 136.34 180 top
R4288  22  [R0402]  15.73 91.63 270 top
R4289  0  [R0402]  12.22 97.03 90 top
R4290  10K  [R0402]  5.56 102.79 90 bottom
R4292  0  [R0402]  6.33 100.91 270 bottom
R4293  0  [R0603]  1.72 105.65 90 bottom
R4294  0  [R0402]  31.81 122.54 90 top
R4295  0  [R0402]  56.29 122.86 90 top
R4296  0  [R0402]  80.32 122.8 90 top
R4297  0  [R0402]  102.85 122.08 90 top
R4298  0  [R0402]  128.2 123.18 180 top
R4299  0  [R0402]  152.42 123.08 90 top
R4300  0  [R0402]  155.72 128.46 90 bottom
R4301  0  [R0402]  131.79 128.14 90 bottom
R4302  0  [R0402]  107.17 128.46 90 bottom
R4303  0  [R0402]  83.65 127.11 90 bottom
R4304  0  [R0402]  59.96 127.36 90 bottom
R4305  0  [R0402]  32.34 126.59 90 bottom
R4308  0.001  [R1206XA]  180.09 43.3 0 bottom
R4309  0.001  [R1206XA]  184.5 47.3 0 top
R4311  0.001  [R1206XA]  184.5 47.3 0 bottom
R4312  4.7K  [R0402]  36.3 109.57 270 top
R4313  4.7K  [R0402]  58.48 109.54 90 top
R4314  4.7K  [R0402]  82.51 108.8 0 top
R4315  4.7K  [R0402]  84.87 106.43 270 bottom
R4316  4.7K  [R0402]  58.68 107.56 270 bottom
R4317  4.7K  [R0402]  39.08 109.22 180 bottom
R4318  4.7K  [R0402]  102.39 108.45 0 top
R4319  4.7K  [R0402]  127.51 110.26 90 top
R4320  4.7K  [R0402]  161.52 129.98 270 top
R4321  4.7K  [R0402]  158.39 109.76 180 bottom
R4322  4.7K  [R0402]  136.76 109.09 180 bottom
R4323  4.7K  [R0402]  109.22 108.8 270 bottom
R4324  33  [R0402]  129.39 38.58 0 top
R4325  33  [R0402]  131.79 35.1 0 top
R4326  33  [R0402]  135.89 41.78 180 top
R4327  33  [R0402]  135.89 42.89 180 top
R4328  10K  [R0402]  83.59 34.43 0 top
R4330  22  [R0402]  79.92 44.18 0 bottom
R4331  22  [R0402]  82.23 43.02 90 bottom
R4332  33  [R0402]  186.27 103.29 270 top
R4333  33  [R0402]  189.62 103.29 270 top
R4334  33  [R0402]  188.52 103.29 270 top
R4335  33  [R0402]  190.71 103.29 270 top
R4336  33  [R0402]  187.39 103.29 270 top
R4337  22  [R0402]  29.7 45.17 0 top
R4338  1K  [R0402]  35.58 33.63 90 top
R4339  1K  [R0402]  36.09 36.15 270 top
R4340  1K  [R0402]  41.1 56.59 90 top
R4341  1K  [R0402]  36.6 33.63 270 top
R4342  1K  [R0402]  37.1 36.15 90 top
R4343  1K  [R0402]  41.1 54.56 270 top
R4356  0  [R0402]  64.11 12.32 180 bottom
R4357  0  [R0402]  58.1 11.71 180 bottom
R4358  4.7K  [R0402]  58.1 12.78 0 bottom
R4361  22  [R0402]  16.06 47.66 90 top
R4362  22  [R0402]  15.84 44.93 0 top
R4363  22  [R0402]  28.67 32.95 90 bottom
R4364  22  [R0402]  30.73 32.38 90 bottom
R4365  22  [R0402]  27.41 36.13 90 bottom
R4366  22  [R0402]  25.47 32.7 90 top
R4367  22  [R0402]  34.14 19.48 180 top
R4368  22  [R0402]  34.14 20.49 180 top
R4369  220  [R0402]  32.91 32.38 90 bottom
R4370  220  [R0402]  23.38 20.76 180 top
R4371  4.7K  [R0402]  32.59 34.53 270 bottom
R4372  4.7K  [R0402]  23.38 21.79 0 top
R4373  4.7K  [R0402]  23.38 22.81 0 top
R4374  22  [R0402]  160.85 18.95 270 top
R4375  22  [R0402]  159.43 18.56 0 top
R4376  1K  [R0402]  29.7 32.38 270 bottom
R4377  1K  [R0402]  30.95 34.57 270 bottom
R4378  1K  [R0402]  28.51 36.13 270 bottom
R4379  1K  [R0402]  26.59 32.7 270 top
R4380  1K  [R0402]  23.38 23.84 0 top
R4381  1K  [R0402]  23.38 27 0 top
R4382  22  [R0402]  48.29 53.75 270 bottom
R4383  0  [R0402]  186.36 134.59 180 top
R4384  0  [R0402]  186.36 138.72 180 top
R4385  100K  [R0402]  9.89 6.81 180 bottom
R4386  47  [R0603]  9.36 2.01 0 bottom
R4387  0  [R0402]  89.32 40.59 180 top
R4388  0  [R0402]  20.13 118.45 180 top
R4389  0  [R0402]  44.64 117.18 180 top
R4390  0  [R0402]  69.94 116.13 180 top
R4391  0  [R0402]  94.72 116.59 180 top
R4392  0  [R0402]  118.12 117.35 180 top
R4393  0  [R0402]  142.3 116.61 180 top
R4394  0  [R0402]  167.09 120.24 0 bottom
R4395  0  [R0402]  139.32 117.53 0 bottom
R4396  0  [R0402]  115.78 116.56 0 bottom
R4397  0  [R0402]  90.08 116.96 0 bottom
R4398  0  [R0402]  66.66 116.22 0 bottom
R4399  0  [R0402]  42.73 119 0 bottom
SW4  -  [SW4P_PS022-N12AAK-1]  178.46 136.22 0 top
SW5  SW3P_SC12P-ACWQR  [SW_RD15P4P]  104.33 143.15 270 top
SW6  -  [SW4S_NDTQ010-G1A-AEAT]  169.8 144.65 0 top
TP1  TP  [TP26D10]  58.28 126.67 0 top
TP2  TP  [TP26D10]  58.69 124.94 0 top
TP3  TP  [TP26D10]  35.12 123.2 0 top
TP4  TP  [TP26D10]  34.16 124.11 0 top
TP5  TP  [TP26D10]  31.12 145.68 0 top
TP6  TP  [TP26D10]  23.23 139.63 0 top
TP7  TP  [TP26D10]  56.59 144.69 0 top
TP8  TP  [TP26D10]  55.06 144.6 0 top
TP9  TP  [TP26D10]  127.31 138.13 180 bottom
TP10  TP  [TP26D10]  125.95 138.59 180 bottom
TP11  TP  [TP26D10]  153.81 144.55 0 top
TP12  TP  [TP26D10]  152.44 144.08 0 top
TP13  TP  [TP26D10]  80.46 144.02 0 top
TP14  TP  [TP26D10]  79.18 144.02 0 top
TP15  TP  [TP26D10]  92.57 145.45 0 top
TP16  TP  [TP26D10]  92.88 144.04 0 top
TP17  TP  [TP26D10]  106.28 123.73 0 top
TP18  TP  [TP26D10]  106.36 125.3 0 top
TP19  TP  [TP26D10]  82.49 125.36 0 top
TP20  TP  [TP26D10]  82.45 126.72 0 top
TP21  TP  [TP26D10]  154.93 124.11 0 top
TP22  TP  [TP26D10]  154.63 125.48 0 top
TP23  TP  [TP26D10]  130.45 124.04 0 top
TP24  TP  [TP26D10]  130.44 125.56 0 top
TP25  TP  [TP26D10]  23.52 129.12 0 top
TP26  TP  [TP26D10]  26.01 128.53 0 top
TP27  TP  [TP26D10]  53.2 123.04 0 top
TP28  TP  [TP26D10]  52.52 124.16 0 top
TP29  TP  [TP26D10]  76.39 123.35 0 top
TP30  TP  [TP26D10]  76.1 124.64 0 top
TP31  TP  [TP26D10]  100.4 123.97 0 top
TP32  TP  [TP26D10]  79.71 145.21 0 top
TP33  TP  [TP26D10]  124.42 124.79 0 top
TP34  TP  [TP26D10]  124.42 123.52 0 top
TP35  TP  [TP26D10]  148.6 123.5 0 top
TP36  TP  [TP26D10]  148.61 124.77 0 top
TP37  TP  [TP26D10]  40.12 123.86 0 top
TP38  TP  [TP26D10]  34.44 144.25 0 top
TP39  TP  [TP26D10]  75.35 145.25 0 top
TP40  TP  [TP26D10]  74.97 144.03 0 top
TP41  TP  [TP26D10]  83.44 144.06 0 top
TP42  TP  [TP26D10]  82.05 144.07 0 top
TP43  TP  [TP26D10]  94.37 145.47 0 top
TP44  TP  [TP26D10]  94.48 144.04 0 top
TP45  TP  [TP26D10]  131.75 142.16 180 bottom
TP46  TP  [TP26D10]  128.71 139.93 180 bottom
TP47  TP  [TP26D10]  159.03 144.23 0 top
TP48  TP  [TP26D10]  157.35 144.22 0 top
TP49  TP  [TP26D10]  34.95 121.87 0 top
TP50  TP  [TP26D10]  59.2 123.72 0 top
TP51  TP  [TP26D10]  83.01 123.8 0 top
TP52  TP  [TP26D10]  106.26 126.57 0 top
TP53  TP  [TP26D10]  130.65 122.68 0 top
TP54  TP  [TP26D10]  154.31 126.84 0 top
TP55  TP  [TP26D10]  32.57 144.38 0 top
TP56  TP  [TP26D10]  57.88 144.67 0 top
TP57  TP  [TP26D10]  81.03 145.21 0 top
TP58  TP  [TP26D10]  97.91 141.4 180 bottom
TP59  TP  [TP26D10]  127.44 136.84 180 bottom
TP60  TP  [TP26D10]  155.22 144.44 0 top
TP61  TP  [TP26D10]  160.04 15.49 0 top
TP62  TP  [TP26D10]  159.45 16.78 0 top
TP63  TP  [TP26D10]  9.07 39.98 0 top
TP64  TP  [TP26D10]  10.52 40.06 0 top
TP65  TP  [TP30]  157.7 18.5 0 top
TP66  TP  [TP30]  157.7 15.96 0 top
TP67  TP  [TP30]  157.7 13.42 0 top
U2  INA230AIRGTR  [QFN16_THXI]  98.37 36.49 270 bottom
U6  M24128-BWMN6TP  [SOIC8XH]  14.2 32.61 90 top
U7  TMP75  [MSOP8]  14.83 74.33 90 bottom
U8  TMP75  [MSOP8]  157.24 53.33 0 bottom
U19  NCP45750IMN24TWG  [DFN12_TH_0-5_3X3XA]  24.81 116 90 top
U20  NCP45750IMN24TWG  [DFN12_TH_0-5_3X3XA]  49.52 115.59 90 top
U21  NCP45750IMN24TWG  [DFN12_TH_0-5_3X3XA]  74.43 114.53 90 top
U22  NCP45750IMN24TWG  [DFN12_TH_0-5_3X3XA]  99.83 115.32 90 top
U23  NCP45750IMN24TWG  [DFN12_TH_0-5_3X3XA]  123.78 115.46 90 top
U24  NCP45750IMN24TWG  [DFN12_TH_0-5_3X3XA]  151.37 114.86 90 top
U25  SN74LVC08APWR  [TSSOP14]  13.74 86.41 270 top
U26  SN74LVC08APWR  [TSSOP14]  14.83 103.89 90 top
U28  NCP45750IMN24TWG  [DFN12_TH_0-5_3X3XA]  38.24 116.74 90 bottom
U29  NCP45750IMN24TWG  [DFN12_TH_0-5_3X3XA]  60.83 114.31 90 bottom
U30  NCP45750IMN24TWG  [DFN12_TH_0-5_3X3XA]  85.02 114.37 90 bottom
U31  NCP45750IMN24TWG  [DFN12_TH_0-5_3X3XA]  110.66 114.4 90 bottom
U32  NCP45750IMN24TWG  [DFN12_TH_0-5_3X3XA]  134.51 114.9 90 bottom
U33  NCP45750IMN24TWG  [DFN12_TH_0-5_3X3XA]  162.25 117.75 90 bottom
U34  PM8535B-FEI  [BGA1311_1_37-5X37-5]  183.09 80.52 0 top
U47  9ZXL1231EKILF-1K/W  [VFQFPN64_TH_0-5_9X9XA]  63.96 61.28 270 top
U50  SN74LVC08APWR  [TSSOP14]  185.63 142.69 0 top
U54  SN74LVC2G14DBVR  [SOT23-6]  72.44 27.01 180 top
U56  M24128-BRMN6TP  [SO8_1-27_4-9X3-9XA]  178.84 116.28 0 top
U58  SCONN8_ACA-SPI-004-P09  [SOCKET8SXD]  185.51 6.37 270 bottom
U61  ZL30281LDF1  [QFN32_TH_0-5_5X5XL]  119.94 38.43 270 top
U62  NL17SZ00DFT2G  [SC70-5XA]  86.41 38.35 0 top
U63  SN74LVC1G125DBVR  [SOT23-5XE]  88.14 33.83 0 top
U66  TXS0102DCUR  [VSSOP8XB]  183.64 134.35 90 top
U71  74LVC07APW  [TSSOP14]  178.99 122.18 0 top
U72  74LVC07APW  [TSSOP14]  22.13 92.32 90 bottom
U73  INA231AIYFFR  [BGA12_0-4_1-388X1-6445]  36.54 115.09 270 top
U74  INA231AIYFFR  [BGA12_0-4_1-388X1-6445]  61.23 114.94 270 top
U75  INA231AIYFFR  [BGA12_0-4_1-388X1-6445]  86.02 115.52 270 top
U76  INA231AIYFFR  [BGA12_0-4_1-388X1-6445]  111.23 114.46 270 top
U77  INA231AIYFFR  [BGA12_0-4_1-388X1-6445]  135.13 114.59 270 top
U78  INA231AIYFFR  [BGA12_0-4_1-388X1-6445]  163.25 120.8 0 top
U79  INA231AIYFFR  [BGA12_0-4_1-388X1-6445]  26.11 113.13 0 bottom
U80  INA231AIYFFR  [BGA12_0-4_1-388X1-6445]  49.06 114.81 0 bottom
U81  INA231AIYFFR  [BGA12_0-4_1-388X1-6445]  73.7 113.53 0 bottom
U82  INA231AIYFFR  [BGA12_0-4_1-388X1-6445]  99.11 113.94 0 bottom
U83  INA231AIYFFR  [BGA12_0-4_1-388X1-6445]  122.88 114.26 0 bottom
U84  INA231AIYFFR  [BGA12_0-4_1-388X1-6445]  150.52 117.37 0 bottom
U86  TM4E129BNCZADI3R  [BGA212]  41.45 45.44 180 top
U88  PCA9846PW  [TSSOP16XD]  20.32 72.92 270 top
U89  PCA9846PW  [TSSOP16XD]  28.52 69.13 270 top
U90  PCA9846PW  [TSSOP16XD]  35.84 69.11 270 top
U91  PCA9846PW  [TSSOP16XD]  22.1 32.21 270 top
U92  PCA9846PW  [TSSOP16XD]  43.43 69.11 270 top
U93  PCA9846PW  [TSSOP16XD]  28.04 88.34 270 top
U94  LCMXO2-1200UHC-4FTG256C  [BGA256D]  15.95 52.15 0 bottom
U95  SN74LVC2G32DCUR  [SOP8]  5.31 83.17 180 top
U96  SN74LVC2G32DCUR  [SOP8]  3.57 77.91 270 top
U97  SN74LVC2G32DCUR  [SOP8]  5.34 89.68 180 top
U98  SN74LVC2G32DCUR  [SOP8]  5.37 92.84 180 top
U99  SN74LVC2G32DCUR  [SOP8]  5.31 86.34 180 top
U100  SN74LVC2G32DCUR  [SOP8]  5.37 96 180 top
U101  PCA9555AHF  [HWQFN24_0-5_4X4]  79.79 51.59 0 bottom
U102  74LVC07APW  [TSSOP14]  192.08 111.71 90 bottom
U103  74LVC07APW  [TSSOP14]  191.64 117.74 90 top
U104  74LVC07APW  [TSSOP14]  95.71 59.18 0 top
U105  74LVC07APW  [TSSOP14]  36.07 86.79 90 top
U106  PCA9517ADP  [TSSOP8_3]  136.05 37.44 0 top
U107  SN74LVC1G07DCKR  [SC70-5XB]  60.94 12.32 180 bottom
U108  PCA9846PW  [TSSOP16XD]  30.19 29.15 270 top
X1  TP_TDR_4P_DIP  [MPKT4_H025P0200]  410.75 -161.66 0 bottom
X2  TP_TDR_4P_DIP  [MPKT4_H025P0200]  260.44 -159.12 180 bottom
X3  TP_TDR_4P_DIP  [MPKT4_H025P0200]  260.44 -163.94 180 bottom
X4  TP_TDR_4P_DIP  [MPKT4_H025P0200]  410.82 -166.51 0 bottom
X5  TP_TDR_4P_DIP  [MPKT4_H025P0200]  260.44 -156.83 180 top
X6  TP_TDR_4P_DIP  [MPKT4_H025P0200]  409.87 -154.29 0 top
X7  TP_TDR_4P_DIP  [MPKT4_H025P0200]  410.82 -168.77 0 top
X8  TP_TDR_4P_DIP  [MPKT4_H025P0200]  260.44 -171.31 180 top
Y2  25MHZ  [X_4S_7M25000083_3-2X2-5]  108.64 38.33 270 top

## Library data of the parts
C1 C2 C6 C9 C12 C15 C18 C21 C24 C27 C30 C33 C36 C39 C44-C46 C49 C70 C87 C89 C92 C94 C97 C100 C103 C121 C122 C125 C128 C131 C134 C137 C140-C145 C197 C204-C206 C213-C215 C222-C224 C231-C233 C240-C242 C249 C250 C258-C263 C267 C270 C273 C275 C277 C280 C537-C543 C545-C579 C592-C607 C609-C612 C618-C644 C651-C654 C656-C666 C675-C694 C715-C724 C728-C730 C732-C734 C759 C761 C765 C769 C771-C776 C909 C910 C949 C950 C952 C953 C975 C1074 C1075 C1078 C1079 C1082 C1083 PC110 PC310 = CAP_NP: signal model: DEFAULT_CAPACITOR_100000pF_2_1
C104 C123 C126 C129 C132 C135 C266 C269 C271 C274 C276 C279 C912 C913 C951 C970 C971 = CAP_NP: signal model: DEFAULT_CAPACITOR_10000pF_2_1
C146-C151 C153 C155 C157 C159 C161 C163 C165 C167 C169 C171 C173 C175 C177 C179 C181 C183 C185 C187 C199 C201 C203 C208 C210 C212 C217 C219 C221 C226 C228 C230 C235 C237 C239 C244 C246 C248 C251 C264 C265 C268 C272 C278 C580-C586 C770 C948 PC102-PC104 PC201-PC203 PC302 PC304 = CAP_NP: signal model: DEFAULT_CAPACITOR_1e+07pF_2_1
C152 C154 C156 C158 C160 C162 C164 C166 C168 C170 C172 C174 C176 C178 C180 C182 C184 C186 C198 C200 C202 C207 C209 C211 C216 C218 C220 C225 C227 C229 C234 C236 C238 C243 C245 C247 C760 C762 C806 C959-C961 C964-C968 C972-C974 PC105 PC107 PC204 PC206 PC305 PC307 = CAP_NP: signal model: DEFAULT_CAPACITOR_1e+06pF_2_1
C188-C193 C252-C257 C587-C591 C969 = CAP_NP: signal model: DEFAULT_CAPACITOR_1e+08pF_2_1
C377-C440 C875-C906 C1010-C1041 C1058-C1073 = CAP_NP: signal model: DEFAULT_CAPACITOR_220000pF_2_1
C613 C615-C617 C645-C650 C667-C674 C749-C752 PC205 PC306 = CAP_NP: signal model: DEFAULT_CAPACITOR_4.7e+06pF_2_1
C614 C655 = CAP_NP: signal model: DEFAULT_CAPACITOR_4.7e+07pF_2_1
C954 = CAP_NP: signal model: DEFAULT_CAPACITOR_15.000000pF_2_1
C955 = CAP_NP: signal model: DEFAULT_CAPACITOR_16.000000pF_2_1
C1085-C1108 C1111-C1149 C1151-C1187 C1189 C1191-C1252 PC106 PC117 PC120 PC215 PC315 PC317 PC322 PC601-PC607 PC610 PC611 PC615 PC701-PC704 = CAP_NP
D1 D5 = LED_12
D3 D17 = LED_0
D4 U106 = PCA9517DP
D18 = DIODE
DM10 = DUMMY_SYMBOL
H1 H2 H7-H30 = HOLE_N
H3-H6 H31 = GND_HOLE
H32-H36 = HOLE
J4 J6 J8 J34 J36 J38 = SCONN134_MDT670M01005
J9-J20 J51-J54 = PICOPROBE_B
J24-J26 J50 = TDR_3P_TH2
J41 = SCONN120_6108312150QLF
J46 J59 = DIP_2PIN
J47 = SCONN8_5153000801V01
J49 = SCONN160_6108316150QLF
J55 = SCONN5_475900001
J56 = SCONN4_502280047N001
J58 = SCONN8_5022800871001
J60 = SCONN5_1051330011
L6 = L: signal model: DEFAULT_RESISTOR_330.000000OHM_2_1
L7 L8 = L: signal model: DEFAULT_INDUCTOR_10000nH_2_1
L11 L13 L14 PL601 PL701 PL702 = L
OSC1 = OSC-4
PC101 PC301 = CAPACITOR_POL: signal model: DEFAULT_CAPACITOR_1e+08pF_2_1
PC108 PC207 PC308 = CAP_NP: signal model: DEFAULT_CAPACITOR_470000pF_2_1
PC109 PC309 = CAP_NP: signal model: DEFAULT_CAPACITOR_150.000000pF_2_1
PC112 PC113 PC210 PC211 PC311-PC313 = CAP_NP: signal model: DEFAULT_CAPACITOR_2.2e+07pF_2_1
PC114 PC212 = CAPACITOR_POL: signal model: DEFAULT_CAPACITOR_2.2e+08pF_2_1
PC115 PC116 PC118 PC119 PC213 PC214 PC216 PC316 PC318-PC321 PC612 = CAPACITOR_POL
PC314 = CAP_NP: signal model: DEFAULT_CAPACITOR_2.2e+08pF_2_1
PJ1 = JUMPER-2_1
PL101 PL201 PL301 = L: signal model: DEFAULT_INDUCTOR_600.000000nH_2_1
PL102 = L: signal model: DEFAULT_INDUCTOR_100.000000nH_2_1
PR101 PR201 PR301 = R: signal model: DEFAULT_RESISTOR_60400OHM_2_1
PR103 PR104 PR106 PR124-PR128 PR203 PR205-PR208 PR303 PR304 PR306 PR601-PR606 PR701 R2910 R3004 R3005 R3098 R3227 R3241 R3565-R3576 R3601 R3619 R3622 R3623 R3625 R3626 R3630-R3634 R3638-R3640 R3645-R3647 R3651-R3654 R3658-R3661 R3669-R3671 R3678 R3691 R3694-R3698 R3701-R3705 R3708-R3713 R3716-R3720 R3723-R3732 R3745-R3747 R3749-R3751 R3753-R3755 R3765 R3766 R3786-R3803 R3806-R3808 R3819-R3825 R3832-R3838 R3845-R3851 R3858-R3864 R3871-R3877 R3882-R3884 R3887-R3894 R3899-R3906 R3908-R3910 R3913-R3916 R3922 R3923 R4048 R4051 R4052 R4055 R4056 R4065-R4067 R4069-R4071 R4073-R4076 R4097-R4145 R4158 R4161-R4163 R4182-R4193 R4206-R4227 R4230 R4231 R4233-R4257 R4262-R4287 R4289 R4290 R4292 R4293 R4308 R4309 R4311-R4323 R4328 R4338-R4343 R4356-R4358 R4369-R4373 R4376-R4381 R4385-R4399 = R
PR105 R3264 = R: signal model: DEFAULT_RESISTOR_15000OHM_2_1
PR107 PR108 PR122 PR307 PR308 R19 R21 R23 R24 R2848 R3049 R3219 = R: signal model: DEFAULT_RESISTOR_10000OHM_2_1
PR109 PR204 PR309 R2916 R2917 = R: signal model: DEFAULT_RESISTOR_2.200000OHM_2_1
PR120 = R: signal model: DEFAULT_RESISTOR_56000OHM_2_1
PR121 = R: signal model: DEFAULT_RESISTOR_12400OHM_2_1
PR123 = R: signal model: DEFAULT_RESISTOR_30100OHM_2_1
PR202 = R: signal model: DEFAULT_RESISTOR_24900OHM_2_1
PR305 = R: signal model: DEFAULT_RESISTOR_34800OHM_2_1
PR320 = R: signal model: DEFAULT_RESISTOR_5600OHM_2_1
PR321 = R: signal model: DEFAULT_RESISTOR_10500OHM_2_1
PU7 = MP1602GTF12Z
PU101 PU201 PU601 = MPQ8645PGVT6001Z
PU301 = MPQ8645PGVTZ
Q9 Q10 Q24 = MOSFET_DUAL_6P
Q36 Q38-Q40 Q42 Q43 Q53 = MOSFET_N_0
Q44 Q46-Q48 Q50 = MOSFET_PCH_GDS
Q45 Q49 Q51 = MOSFET_NCH_GATE_PRO_DIODE_GDS
Q52 = MOSFET_N_GSD
R3 R4 R9 R10 R41-R44 R47 R48 R2958 R2959 R3044 R3045 R3187-R3210 R3242 R3270 R3281 R3282 R3287-R3298 R3474 R3511-R3534 R3551 R3552 R3577-R3600 R3618 R3620 R3621 R3628 R3629 R3635 R3636 R3642 R3643 R3649 R3650 R3656 R3657 R3666 R3667 R3692 R3693 R3699 R3700 R3706 R3707 R3714 R3715 R3721 R3722 R3748 R3752 R3756-R3759 R3764 R3767-R3784 R3804 R3805 R3809-R3818 R3826-R3831 R3839-R3844 R3852-R3857 R3865-R3870 R3878-R3881 R3885 R3911 R3912 R3917-R3921 R3924-R4035 R4049 R4050 R4053 R4054 R4057-R4064 R4068 R4072 R4077-R4096 R4146-R4157 R4159 R4160 R4164-R4175 R4194-R4205 R4228 R4229 R4232 R4288 R4330 R4331 R4337 R4361-R4368 R4374 R4375 R4382-R4384 = R: signal model: DEFAULT_RESISTOR_0.001OHM_2_1
R6 = Q_SP_RES4P
R7 R8 = R: signal model: DEFAULT_RESISTOR_10.000000OHM_2_1
R15 = R: signal model: DEFAULT_RESISTOR_51.000000OHM_2_1
R16 R67-R78 R91-R96 R2774 R2777 R2780 R2783 R2786 R2789 R2791-R2796 R2799 R2800 R2833-R2844 R2849-R2854 R2885 R2886 R2888 R2889 R2891 R2892 R2894 R2895 R2897 R2898 R2900 R2901 R2918-R2941 R3043 R3046 R3047 R3055 R3063-R3074 R3136-R3160 R3256-R3261 R3285 R3301 R3302 R3336 R3337 R3430-R3432 R3535-R3546 = R: signal model: DEFAULT_RESISTOR_4700OHM_2_1
R17 R18 R20 R22 = R: signal model: DEFAULT_RESISTOR_220.000000OHM_2_1
R2847 R2960 R3123 R3124 = R: signal model: DEFAULT_RESISTOR_100000OHM_2_1
R2864-R2869 R2949-R2954 = R: signal model: DEFAULT_RESISTOR_49.900000OHM_2_1
R2875 = R: signal model: DEFAULT_RESISTOR_2700OHM_2_1
R2961 R3268 R3269 = R: signal model: DEFAULT_RESISTOR_150.000000OHM_2_1
R2963 R2969-R2971 R3125-R3132 R3161 R3162 R3218 R3220 R3230-R3237 R3240 R3265 R3433-R3435 = R: signal model: DEFAULT_RESISTOR_1000.000000OHM_2_1
R2964 R2966-R2968 R3216 R3217 R3271-R3273 R3275-R3279 R3284 = R: signal model: DEFAULT_RESISTOR_4750OHM_2_1
R3048 R3121 = R: signal model: DEFAULT_RESISTOR_100.000000OHM_2_1
R3050 R3053 R3054 R3099 R3100 R3212-R3215 R3250-R3255 R3266 R3274 R3280 R3332-R3335 R4258-R4261 R4324-R4327 R4332-R4336 = R: signal model: DEFAULT_RESISTOR_33.000000OHM_2_1
